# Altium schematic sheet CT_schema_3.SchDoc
size 379 x 228 mm
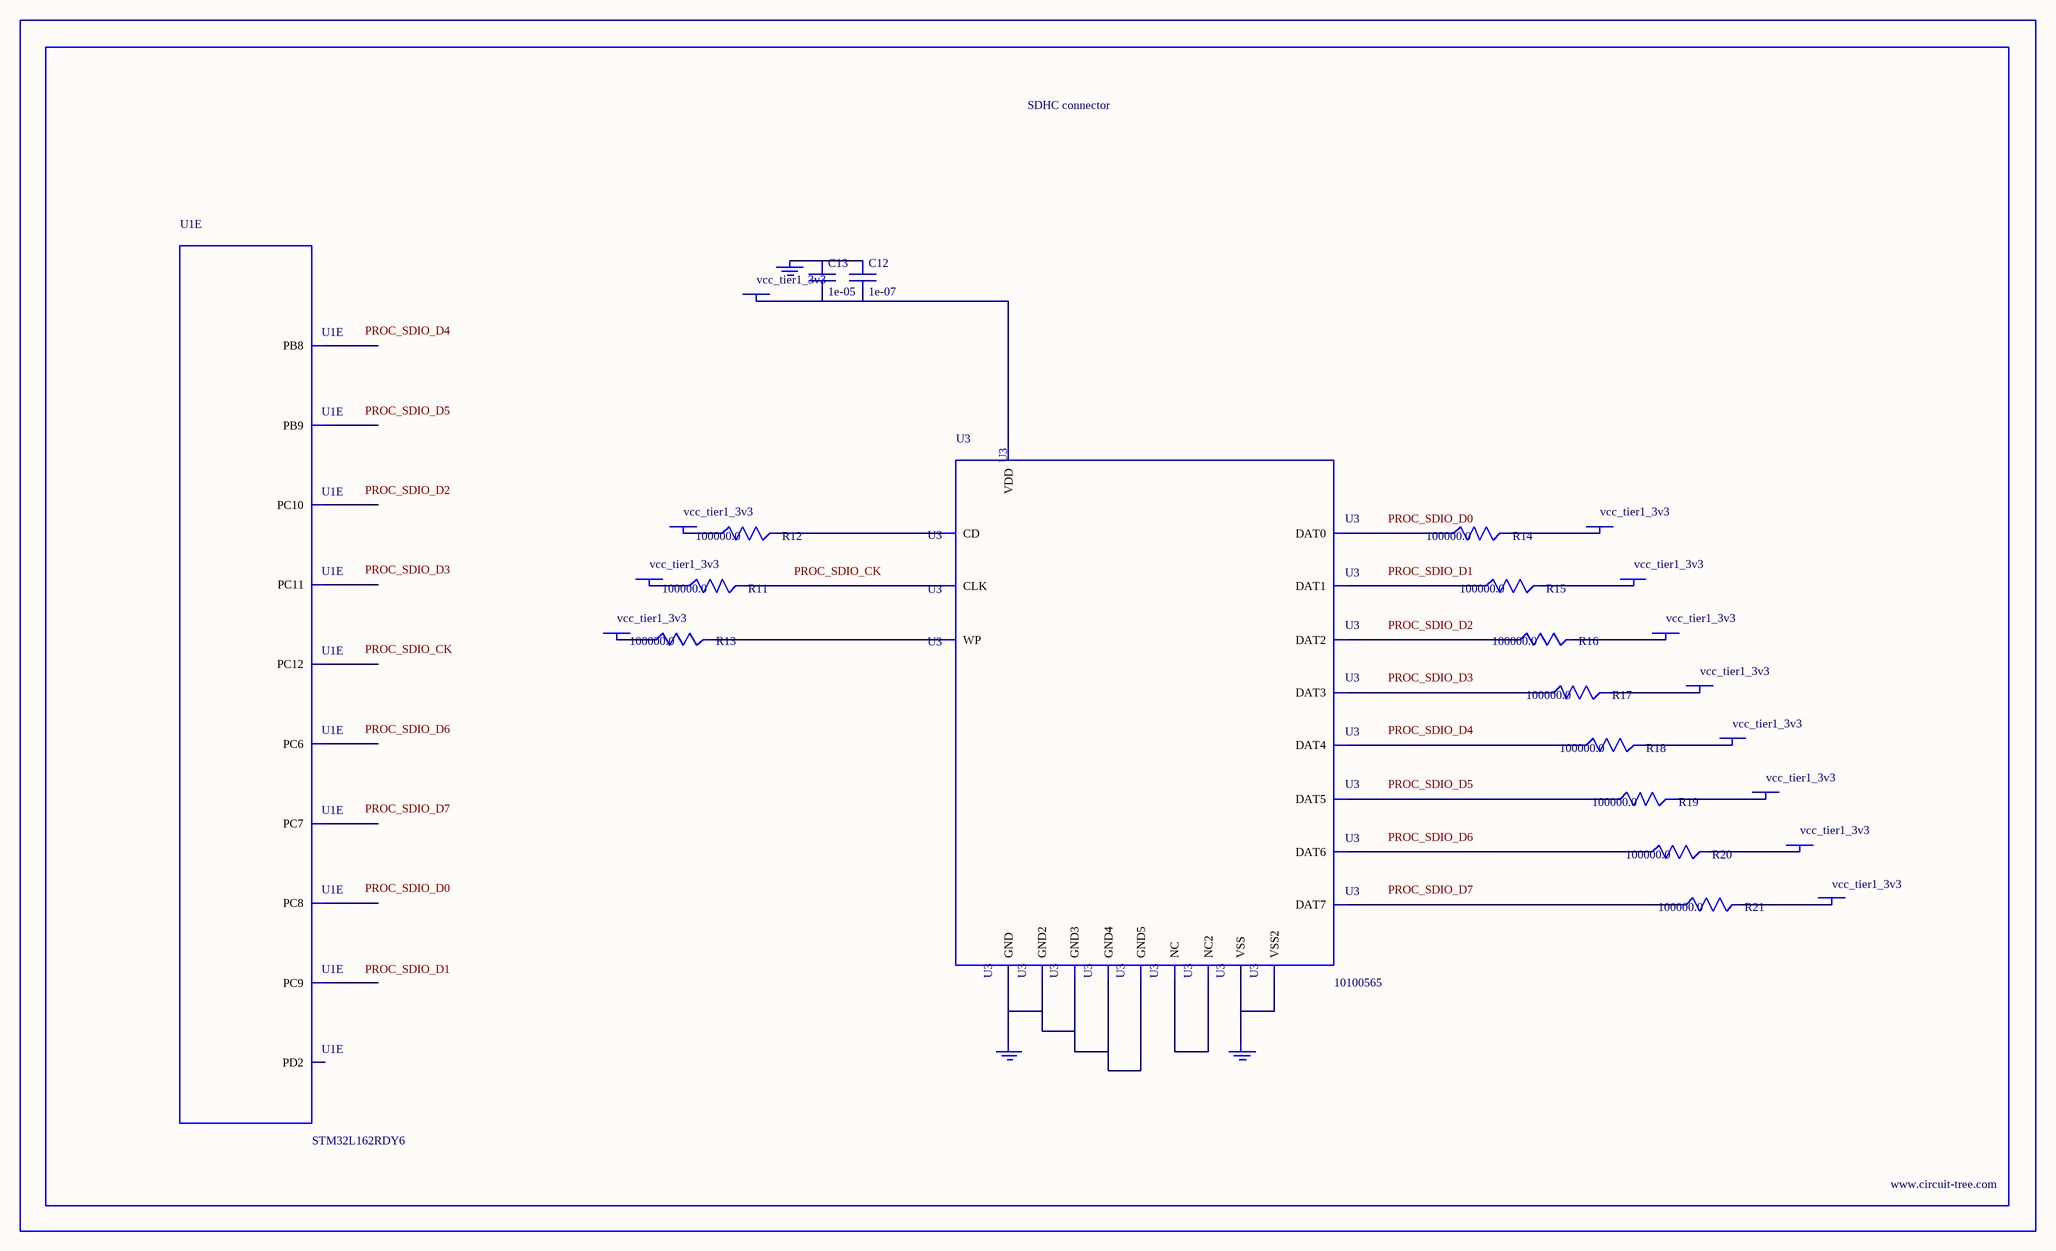
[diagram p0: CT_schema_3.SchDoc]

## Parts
BORDER2  (no value)
C12  1e-07  [C0402]
C13  1e-05  [C0805]
GND_INSTANCE_2_0  (no value)
GND_INSTANCE_2_1  (no value)
GND_INSTANCE_2_2  (no value)
POWER_INSTANCE_2_0  vcc_tier1_3v3
POWER_INSTANCE_2_1  vcc_tier1_3v3
POWER_INSTANCE_2_2  vcc_tier1_3v3
POWER_INSTANCE_2_3  vcc_tier1_3v3
POWER_INSTANCE_2_4  vcc_tier1_3v3
POWER_INSTANCE_2_5  vcc_tier1_3v3
POWER_INSTANCE_2_6  vcc_tier1_3v3
POWER_INSTANCE_2_7  vcc_tier1_3v3
POWER_INSTANCE_2_8  vcc_tier1_3v3
POWER_INSTANCE_2_9  vcc_tier1_3v3
POWER_INSTANCE_2_10  vcc_tier1_3v3
POWER_INSTANCE_2_11  vcc_tier1_3v3
R11  100000.0  [R0603]
R12  100000.0  [R0603]
R13  100000.0  [R0603]
R14  100000.0  [R0603]
R15  100000.0  [R0603]
R16  100000.0  [R0603]
R17  100000.0  [R0603]
R18  100000.0  [R0603]
R19  100000.0  [R0603]
R20  100000.0  [R0603]
R21  100000.0  [R0603]
U1  STM32L162RDY6  [WLCSP64]  (part E of 6)
U3  10100565  [10100565]

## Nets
NetC12_1: C12.1 C13.1 GND_INSTANCE_2_0.0(GND)
NetC12_2: C12.2 C13.2 POWER_INSTANCE_2_7.0(PWR) U3.9(VDD)
NetGND_INSTANCE_2_1_0: GND_INSTANCE_2_1.0(GND) U3.6(VSS) U3.10(VSS2)
NetGND_INSTANCE_2_2_0: GND_INSTANCE_2_2.0(GND) U3.12(GND) U3.16(GND2) U3.17(GND3) U3.20(GND4) U3.21(GND5)
NetPOWER_INSTANCE_2_0_0: POWER_INSTANCE_2_0.0(PWR) R13.1
NetPOWER_INSTANCE_2_1_0: POWER_INSTANCE_2_1.0(PWR) R12.1
NetPOWER_INSTANCE_2_2_0: POWER_INSTANCE_2_2.0(PWR) R15.2
NetPOWER_INSTANCE_2_3_0: POWER_INSTANCE_2_3.0(PWR) R14.2
NetPOWER_INSTANCE_2_4_0: POWER_INSTANCE_2_4.0(PWR) R21.2
NetPOWER_INSTANCE_2_5_0: POWER_INSTANCE_2_5.0(PWR) R20.2
NetPOWER_INSTANCE_2_6_0: POWER_INSTANCE_2_6.0(PWR) R11.1
NetPOWER_INSTANCE_2_8_0: POWER_INSTANCE_2_8.0(PWR) R19.2
NetPOWER_INSTANCE_2_9_0: POWER_INSTANCE_2_9.0(PWR) R18.2
NetPOWER_INSTANCE_2_10_0: POWER_INSTANCE_2_10.0(PWR) R17.2
NetPOWER_INSTANCE_2_11_0: POWER_INSTANCE_2_11.0(PWR) R16.2
NetR11_2: R11.2 U3.8(CLK)
NetR12_2: R12.2 U3.2(CD)
NetR13_2: R13.2 U3.1(WP)
NetR14_1: R14.1 U3.4(DAT0)
NetR15_1: R15.1 U3.3(DAT1)
NetR16_1: R16.1 U3.15(DAT2)
NetR17_1: R17.1 U3.14(DAT3)
NetR18_1: R18.1 U3.13(DAT4)
NetR19_1: R19.1 U3.11(DAT5)
NetR20_1: R20.1 U3.7(DAT6)
NetR21_1: R21.1 U3.5(DAT7)
NetU3_18: U3.18(NC) U3.19(NC2)

Not connected (* = marked no-connect by the designer): U1 A2(PC10) A3(PD2) B3(PC11) B6(PB9) C4(PC12) D1(PC9) D5(PB8) E1(PC6) E2(PC7) E3(PC8)

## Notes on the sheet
- Labels drawn without touching a wire or pin: PROC_SDIO_CK, PROC_SDIO_D0, PROC_SDIO_D1, PROC_SDIO_D2, PROC_SDIO_D3, PROC_SDIO_D4, PROC_SDIO_D5, PROC_SDIO_D6, PROC_SDIO_D7

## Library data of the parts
BORDER2 = BORDER_PAGE2
C12 = C0402C104K3RACTU
C13 = C0805C106K8RACTU
GND_INSTANCE_2_0-GND_INSTANCE_2_2 = GND
POWER_INSTANCE_2_0-POWER_INSTANCE_2_11 = PWR
R11-R21 = RC0603JR-07100KL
